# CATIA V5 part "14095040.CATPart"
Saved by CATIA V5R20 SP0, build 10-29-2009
Part number: 14095040
Definition: NONE
Nomenclature: 14095040
Source: Unknown
Description: 14095040
Bounding box of the stored display mesh (mm): x -20 to 80, y -61.5 to 51.6, z -51.6 to 51.6
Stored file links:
  C:\Users\Utente\Desktop\IO LAVORO\3D X SITO CF\X SITO\PLASTICA\RF2\14095040.CATPart
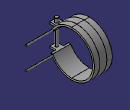
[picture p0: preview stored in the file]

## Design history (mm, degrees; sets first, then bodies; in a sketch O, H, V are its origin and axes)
Body1 "14095040" (main body)
  Solid1: solid without history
